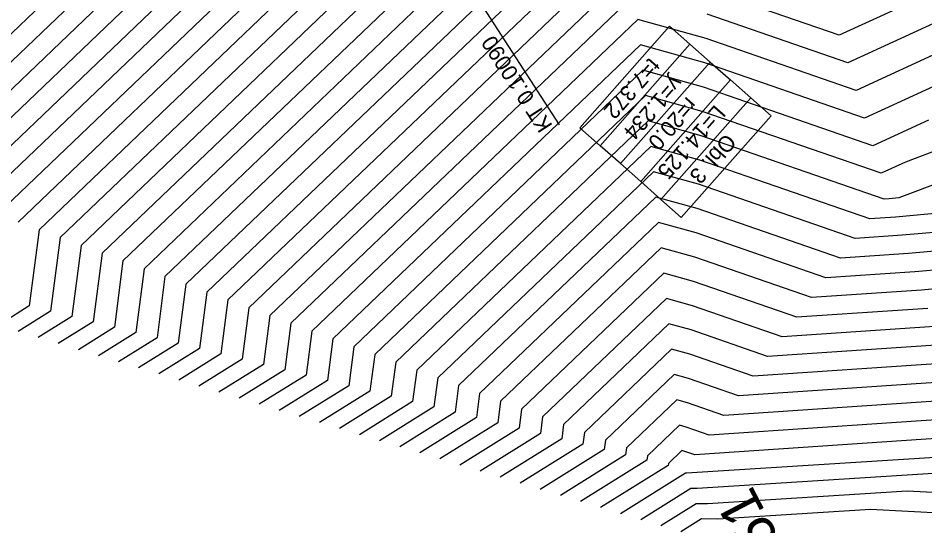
# Model space of a CAD drawing. Extents: x -549394 to -546608, y -1037055 to -1033629.
# Drawn here: x -547510.8 to -547310, y -1036274.8 to -1036162.3 of the extents above; entities that cross this region are included whole.
import ezdxf

# ---------------------------------------------------------------- set-up
doc = ezdxf.new("R2010")
doc.units = 0
for name, color, linetype in [('hlavni_vrst', 7, 'Continuous'), ('norm_vrst', 7, 'Continuous'), ('x_popis_oblouky_C412', 7, 'Continuous'), ('x_popis_pricne_rezy_C412', 7, 'Continuous')]:
    doc.layers.add(name, color=color, linetype=linetype)

msp = doc.modelspace()

# ---------------------------------------------------------------- linework, layer by layer
at = {"layer": 'hlavni_vrst'}
for p, q in [((-547383.95, -1036061.55), (-547529.34, -1036200.56)), ((-547381.07, -1036089.63), (-547506.12, -1036209.19)), ((-547378.19, -1036117.71), (-547482.89, -1036217.82)), ((-547375.3, -1036145.78), (-547459.67, -1036226.45)), ((-547372.42, -1036173.86), (-547436.45, -1036235.08)), ((-547359.01, -1036177.61), (-547372.42, -1036173.86)), ((-547321.53, -1036190.57), (-547359.01, -1036177.61)), ((-547309.19, -1036184.88), (-547321.53, -1036190.57)), ((-547369.54, -1036201.94), (-547413.23, -1036243.71)), ((-547360.39, -1036204.49), (-547369.54, -1036201.94)), ((-547328.68, -1036215.46), (-547360.39, -1036204.49)), ((-547506.12, -1036209.19), (-547508.3, -1036226.06)), ((-547283.64, -1036211.83), (-547313.63, -1036214.46)), ((-547313.63, -1036214.46), (-547328.68, -1036215.46)), ((-547482.89, -1036217.82), (-547484.72, -1036231.95)), ((-547508.3, -1036226.06), (-547515.2, -1036230.37)), ((-547459.67, -1036226.45), (-547461.15, -1036237.83)), ((-547366.66, -1036230.02), (-547390.01, -1036252.34)), ((-547361.77, -1036231.38), (-547366.66, -1036230.02)), ((-547344.82, -1036237.24), (-547361.77, -1036231.38)), ((-547484.72, -1036231.95), (-547492.97, -1036237.09)), ((-547436.45, -1036235.08), (-547437.57, -1036243.72)), ((-547306.47, -1036234.68), (-547344.82, -1036237.24)), ((-547461.15, -1036237.83), (-547470.74, -1036243.82)), ((-547437.57, -1036243.72), (-547448.51, -1036250.54)), ((-547413.23, -1036243.71), (-547413.99, -1036249.61)), ((-547413.99, -1036249.61), (-547426.28, -1036257.27)), ((-547390.01, -1036252.34), (-547390.42, -1036255.49)), ((-547299.32, -1036254.9), (-547360.96, -1036259.03)), ((-547390.42, -1036255.49), (-547404.04, -1036264)), ((-547363.78, -1036258.09), (-547366.79, -1036260.97)), ((-547363.15, -1036258.27), (-547363.78, -1036258.09)), ((-547360.96, -1036259.03), (-547363.15, -1036258.27)), ((-547366.84, -1036261.38), (-547381.81, -1036270.72)), ((-547366.79, -1036260.97), (-547366.84, -1036261.38))]:
    msp.add_line(p, q, dxfattribs=at)
at = {"layer": 'norm_vrst'}
for p, q in [((-547395.55, -1036066.47), (-547533.98, -1036198.84)), ((-547383.37, -1036067.17), (-547524.69, -1036202.29)), ((-547407.14, -1036071.39), (-547538.63, -1036197.11)), ((-547382.8, -1036072.78), (-547520.05, -1036204.01)), ((-547418.74, -1036076.32), (-547543.27, -1036195.38)), ((-547382.22, -1036078.4), (-547515.4, -1036205.74)), ((-547381.64, -1036084.01), (-547510.76, -1036207.47)), ((-547380.49, -1036095.24), (-547501.47, -1036210.92)), ((-547379.92, -1036100.86), (-547496.83, -1036212.64)), ((-547379.34, -1036106.47), (-547492.18, -1036214.37)), ((-547378.76, -1036112.09), (-547487.54, -1036216.1)), ((-547377.61, -1036123.32), (-547478.25, -1036219.55)), ((-547377.03, -1036128.94), (-547473.61, -1036221.27)), ((-547376.46, -1036134.55), (-547468.96, -1036223)), ((-547375.88, -1036140.17), (-547464.32, -1036224.73)), ((-547289.21, -1036147.79), (-547328.95, -1036166.11)), ((-547374.73, -1036151.4), (-547455.03, -1036228.18)), ((-547374.15, -1036157.01), (-547450.38, -1036229.9)), ((-547328.95, -1036166.11), (-547357.91, -1036156.1)), ((-547293.83, -1036156.89), (-547327.09, -1036172.23)), ((-547373.58, -1036162.63), (-547445.74, -1036231.63)), ((-547358.46, -1036166.85), (-547373.58, -1036162.63)), ((-547327.09, -1036172.23), (-547358.18, -1036161.47)), ((-547325.24, -1036178.34), (-547358.46, -1036166.85)), ((-547298.95, -1036166.22), (-547325.24, -1036178.34)), ((-547373, -1036168.25), (-547441.1, -1036233.36)), ((-547358.74, -1036172.23), (-547373, -1036168.25)), ((-547323.39, -1036184.45), (-547358.74, -1036172.23)), ((-547304.07, -1036175.55), (-547323.39, -1036184.45)), ((-547371.85, -1036179.48), (-547431.81, -1036236.81)), ((-547359.29, -1036182.98), (-547371.85, -1036179.48)), ((-547319.68, -1036196.68), (-547359.29, -1036182.98)), ((-547371.27, -1036185.09), (-547427.16, -1036238.53)), ((-547359.56, -1036188.36), (-547371.27, -1036185.09)), ((-547275.26, -1036186.68), (-547315.79, -1036202.13)), ((-547318.99, -1036202.39), (-547359.56, -1036188.36)), ((-547370.69, -1036190.71), (-547422.52, -1036240.26)), ((-547359.84, -1036193.74), (-547370.69, -1036190.71)), ((-547303.56, -1036190.15), (-547314.31, -1036194.21)), ((-547322.22, -1036206.75), (-547359.84, -1036193.74)), ((-547314.31, -1036194.21), (-547319.68, -1036196.68)), ((-547370.12, -1036196.32), (-547417.87, -1036241.99)), ((-547360.11, -1036199.12), (-547370.12, -1036196.32)), ((-547325.45, -1036211.1), (-547360.11, -1036199.12)), ((-547317.92, -1036202.32), (-547318.99, -1036202.39)), ((-547315.79, -1036202.13), (-547317.92, -1036202.32)), ((-547316.49, -1036206.37), (-547322.22, -1036206.75)), ((-547305.07, -1036205.37), (-547316.49, -1036206.37)), ((-547368.96, -1036207.55), (-547408.59, -1036245.44)), ((-547360.67, -1036209.87), (-547368.96, -1036207.55)), ((-547294.36, -1036208.6), (-547315.06, -1036210.41)), ((-547501.47, -1036210.92), (-547503.59, -1036227.24)), ((-547331.91, -1036219.82), (-547360.67, -1036209.87)), ((-547315.06, -1036210.41), (-547325.45, -1036211.1)), ((-547496.83, -1036212.64), (-547498.87, -1036228.42)), ((-547368.39, -1036213.17), (-547403.94, -1036247.16)), ((-547360.94, -1036215.25), (-547368.39, -1036213.17)), ((-547492.18, -1036214.37), (-547494.16, -1036229.59)), ((-547335.13, -1036224.17), (-547360.94, -1036215.25)), ((-547487.54, -1036216.1), (-547489.44, -1036230.77)), ((-547280.16, -1036215.7), (-547312.2, -1036218.5)), ((-547367.81, -1036218.79), (-547399.3, -1036248.89)), ((-547361.22, -1036220.63), (-547367.81, -1036218.79)), ((-547312.2, -1036218.5), (-547331.91, -1036219.82)), ((-547478.25, -1036219.55), (-547480.01, -1036233.12)), ((-547473.61, -1036221.27), (-547475.29, -1036234.3)), ((-547338.36, -1036228.53), (-547361.22, -1036220.63)), ((-547281.93, -1036220.02), (-547310.77, -1036222.54)), ((-547468.96, -1036223), (-547470.58, -1036235.48)), ((-547310.77, -1036222.54), (-547335.13, -1036224.17)), ((-547464.32, -1036224.73), (-547465.86, -1036236.66)), ((-547367.23, -1036224.4), (-547394.65, -1036250.62)), ((-547361.49, -1036226), (-547367.23, -1036224.4)), ((-547503.59, -1036227.24), (-547510.75, -1036231.71)), ((-547341.59, -1036232.89), (-547361.49, -1036226)), ((-547309.34, -1036226.59), (-547338.36, -1036228.53)), ((-547498.87, -1036228.42), (-547506.31, -1036233.06)), ((-547455.03, -1036228.18), (-547456.43, -1036239.01)), ((-547494.16, -1036229.59), (-547501.86, -1036234.4)), ((-547489.44, -1036230.77), (-547497.41, -1036235.75)), ((-547450.38, -1036229.9), (-547451.72, -1036240.19)), ((-547307.9, -1036230.63), (-547341.59, -1036232.89)), ((-547480.01, -1036233.12), (-547488.52, -1036238.44)), ((-547445.74, -1036231.63), (-547447, -1036241.37)), ((-547441.1, -1036233.36), (-547442.29, -1036242.54)), ((-547475.29, -1036234.3), (-547484.08, -1036239.78)), ((-547470.58, -1036235.48), (-547479.63, -1036241.13)), ((-547465.86, -1036236.66), (-547475.18, -1036242.47)), ((-547431.81, -1036236.81), (-547432.86, -1036244.9)), ((-547366.08, -1036235.63), (-547385.36, -1036254.07)), ((-547362.04, -1036236.76), (-547366.08, -1036235.63)), ((-547348.05, -1036241.6), (-547362.04, -1036236.76)), ((-547456.43, -1036239.01), (-547466.29, -1036245.16)), ((-547427.16, -1036238.53), (-547428.14, -1036246.07)), ((-547305.04, -1036238.72), (-547348.05, -1036241.6)), ((-547451.72, -1036240.19), (-547461.84, -1036246.51)), ((-547447, -1036241.37), (-547457.4, -1036247.85)), ((-547422.52, -1036240.26), (-547423.42, -1036247.25)), ((-547365.51, -1036241.25), (-547380.72, -1036255.79)), ((-547362.32, -1036242.14), (-547365.51, -1036241.25)), ((-547442.29, -1036242.54), (-547452.95, -1036249.2)), ((-547417.87, -1036241.99), (-547418.71, -1036248.43)), ((-547351.28, -1036245.96), (-547362.32, -1036242.14)), ((-547303.61, -1036242.77), (-547351.28, -1036245.96)), ((-547432.86, -1036244.9), (-547444.06, -1036251.89)), ((-547408.59, -1036245.44), (-547409.28, -1036250.78)), ((-547428.14, -1036246.07), (-547439.61, -1036253.23)), ((-547423.42, -1036247.25), (-547435.17, -1036254.58)), ((-547403.94, -1036247.16), (-547404.56, -1036251.96)), ((-547364.93, -1036246.86), (-547376.08, -1036257.52)), ((-547362.59, -1036247.52), (-547364.93, -1036246.86)), ((-547302.18, -1036246.81), (-547354.5, -1036250.31)), ((-547418.71, -1036248.43), (-547430.72, -1036255.92)), ((-547399.3, -1036248.89), (-547399.85, -1036253.14)), ((-547354.5, -1036250.31), (-547362.59, -1036247.52)), ((-547409.28, -1036250.78), (-547421.83, -1036258.62)), ((-547394.65, -1036250.62), (-547395.13, -1036254.32)), ((-547300.75, -1036250.86), (-547357.73, -1036254.67)), ((-547404.56, -1036251.96), (-547417.38, -1036259.96)), ((-547399.85, -1036253.14), (-547412.94, -1036261.31)), ((-547364.35, -1036252.48), (-547371.43, -1036259.25)), ((-547362.87, -1036252.89), (-547364.35, -1036252.48)), ((-547357.73, -1036254.67), (-547362.87, -1036252.89)), ((-547395.13, -1036254.32), (-547408.49, -1036262.65)), ((-547385.36, -1036254.07), (-547385.7, -1036256.67)), ((-547385.7, -1036256.67), (-547399.6, -1036265.34)), ((-547380.72, -1036255.79), (-547380.99, -1036257.85)), ((-547380.99, -1036257.85), (-547395.15, -1036266.69)), ((-547376.27, -1036259.02), (-547390.71, -1036268.03)), ((-547376.08, -1036257.52), (-547376.27, -1036259.02)), ((-547371.43, -1036259.25), (-547371.55, -1036260.2)), ((-547302.54, -1036259.26), (-547362.75, -1036263.13)), ((-547371.55, -1036260.2), (-547386.26, -1036269.38)), ((-547363.04, -1036263.13), (-547377.37, -1036272.07)), ((-547362.75, -1036263.13), (-547363.04, -1036263.13)), ((-547305.81, -1036263.01), (-547360.45, -1036266.52)), ((-547361.84, -1036266.5), (-547372.92, -1036273.41)), ((-547360.45, -1036266.52), (-547361.84, -1036266.5)), ((-547313.91, -1036267.06), (-547358.15, -1036269.9)), ((-547301.16, -1036267.76), (-547313.91, -1036267.06)), ((-547360.64, -1036269.87), (-547368.48, -1036274.76)), ((-547358.15, -1036269.9), (-547360.64, -1036269.87)), ((-547322.02, -1036271.12), (-547355.85, -1036273.29)), ((-547302.83, -1036272.17), (-547322.02, -1036271.12)), ((-547359.45, -1036273.24), (-547364.03, -1036276.1)), ((-547355.85, -1036273.29), (-547359.45, -1036273.24))]:
    msp.add_line(p, q, dxfattribs=at)
at = {"layer": 'x_popis_oblouky_C412'}
msp.add_lwpolyline([(-547413.44, -1036151.19), (-547391, -1036185.95)], dxfattribs=at)
for points in [[(-547362.06, -1036168.07), (-547381.92, -1036190.56), (-547386.42, -1036186.58), (-547366.56, -1036164.1)], [(-547357.57, -1036172.04), (-547377.42, -1036194.53), (-547381.92, -1036190.56), (-547362.06, -1036168.07)], [(-547353.07, -1036176.01), (-547372.92, -1036198.5), (-547377.42, -1036194.53), (-547357.57, -1036172.04)], [(-547348.57, -1036179.98), (-547368.43, -1036202.47), (-547372.92, -1036198.5), (-547353.07, -1036176.01)], [(-547344.07, -1036183.95), (-547363.93, -1036206.44), (-547368.43, -1036202.47), (-547348.57, -1036179.98)]]:
    msp.add_lwpolyline(points, close=True, dxfattribs=at)

# ---------------------------------------------------------------- texts
for s, rotation, p in [('KT 0.10090', 122.9348, (-547392.32, -1036186.13)), ('t=7.372', 228.5797, (-547370.92, -1036170.86)), ('y=1.234', 228.5797, (-547365.85, -1036174.71)), ('r=20.0', 228.5797, (-547362.69, -1036179.53)), ('L=14.125', 228.5797, (-547356.47, -1036181.29)), ('Obl. 3', 228.5797, (-547354.09, -1036187.66))]:
    msp.add_text(s, height=3.5, rotation=rotation, dxfattribs=at).set_placement(p)
at = {"layer": 'x_popis_pricne_rezy_C412'}
msp.add_text('PŘ 5 km 0.1051', height=9.0627, rotation=117.4888, dxfattribs=at).set_placement((-547308.28, -1036342.72))

doc.saveas('drawing.dxf')
